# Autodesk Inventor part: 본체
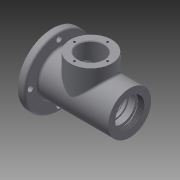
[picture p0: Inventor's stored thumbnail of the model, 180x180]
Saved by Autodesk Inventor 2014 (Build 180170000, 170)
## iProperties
Created: 2016-08
Part Number: 본체
Material: 일반
Document SubType Name: Modeling
Designer: owner
Density: 1 g/cm^3
Appearance: 기본값
Author: owner
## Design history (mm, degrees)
sketch "스케치1"
  geometry: L1 (0, 0)-(-57.5, 0); L2 (-57.5, 0)-(-57.5, 31); L3 (0, 0)-(57.5, 0); L4 (57.5, 0)-(57.5, 31); L5 (57.5, 31)-(54.5, 31); L6 (57.5, 0)-(54.5, 0); L7 (54.5, 31)-(57.5, 31); L8 (57.5, 0)-(57.5, 21); L9 (43.5, 0)-(36.2, 0); L10 (43.5, 0)-(42.8, 0); L11 (36.2, 0)-(33.5, 0); L12 (-44.5, 50)-(-44.5, 31); L13 (-54.5, 50)-(-44.5, 50); L14 (-54.5, 31)-(-54.5, 50); L15 (44.5, 31)-(54.5, 31); L16 (-57.5, 31)-(-54.5, 31); L17 (-44.5, 31)-(44.5, 31)
  constraints: 34 end point, 6 point on line, 3 perpendicular, 1 horizontal
revolve "회전1" sketch "스케치1" stored, may be unused: angle "d19" = 90 deg
sketch "스케치2"
  geometry: L1 (57.5, 0)-(57.5, 21); L2 (57.5, 0)-(43.5, 0); L3 (43.5, 0)-(36.2, 0); L4 (43.5, 0)-(42.8, 0); L5 (36.2, 0)-(33.5, 0); L6 (-45.5, 0)-(-48.5, 0); L7 (-57.5, 0)-(-36.5, 0); L8 (-57.5, 0)-(-31.5, 0); L9 (0.391, 0)-(-18.609, 0); L10 (19.391, 0)-(0.391, 0); L11 (0.391, 0)-(-29.609, 0); L12 (-57.5, 0)-(-31.5, 0); L13 (0.391, 0)-(19.391, 0); L14 (0.391, 0)-(-18.609, 0); L15 (-31.5, 0)-(28.5, 0); L16 (-57.5, 0)-(-1.5, 0); L17 (-45.491, 16.711)-(-57.5, 21); L18 (-28.2, 17.5)-(-17.5, 17.5); L19 (-17.5, 23)-(-17.5, 17.5); L20 (0, 26)-(-14.5, 26); L21 (-43.5, 12.904)-(-43.5, 13.886); L22 (-42.8, 12.5)-(-43.5, 12.904); L23 (-36.5, 12.5)-(-42.8, 12.5); L24 (-36.2, 10)-(-36.2, 12.2); L25 (-33.5, 10)-(-33.5, 13.5); L26 (-33.5, 10)-(-36.2, 10); L27 (-28.5, 16.5)-(-28.5, 17.2); L28 (-30.5, 16.5)-(-28.5, 16.5); L29 (31.5, 17.5)-(20.8, 17.5); L30 (20.5, 23)-(20.5, 17.8); L31 (1.5, 26)-(17.5, 26); L32 (57.5, 21)-(48.5, 21); L33 (45.5, 21)-(45.5, 20); L34 (33.25, 17.5)-(36.5, 17.5); L35 (33.25, 18.5)-(33.25, 17.5); L36 (31.5, 17.5)-(31.5, 18.5); L37 (31.5, 18.5)-(33.25, 18.5); L38 (36.5, 17.5)-(36.5, 20); L39 (36.5, 20)-(45.5, 20); L40 (48.5, 24)-(45.5, 24); L41 (48.5, 21)-(48.5, 24); L42 (45.5, 24)-(45.5, 21); L43 (1.5, 26)-(0, 26); L44 (-57.5, 21)-(-57.5, 0); L45 (57.5, 0)-(-28.5, 0); A1 r 3 centre (-46.5, 13.886) between (-43.5, 13.886) and (-45.491, 16.711); A2 r 0.3 centre (-36.5, 12.2) between (-36.2, 12.2) and (-36.5, 12.5); A3 r 3 centre (-30.5, 13.5) between (-30.5, 16.5) and (-33.5, 13.5); A4 r 0.3 centre (20.8, 17.8) between (20.5, 17.8) and (20.8, 17.5); A5 r 3 centre (-14.5, 23) between (-14.5, 26) and (-17.5, 23); A6 r 3 centre (17.5, 23) between (20.5, 23) and (17.5, 26); A7 r 0.3 centre (-28.2, 17.2) between (-28.2, 17.5) and (-28.5, 17.2); 6 further points
  constraints: 90 end point, 14 point on circle, 8 point on line, 7 centre point, 6 tangent, 4 horizontal, 2 perpendicular, 1 equal radius, 1 midpoint, 14 other
revolve "회전2" sketch "스케치2" stored, may be unused: angle "d62" = 90 deg
node "작업 평면1"
sketch "스케치4"
  geometry: L1 (57.5, -31)-(57.5, 0); C1 r 30 at (1.5, 0); 5 further points
  constraints: 2 end point, 1 centre point
sketch "스케치5"
  geometry: C1 r 4 at (-41.5, 0); C2 r 4 at (41.5, 0); C3 r 4 at (0, 41.5); C4 r 4 at (0, -41.5)
  constraints: 4 centre point
extrude "돌출2" cut sketch "스케치5" distance "d104" = 10; taper "d105" = 0 deg
feature "스레드2" dims "d106" = 10, "d107" = 0
fillet "모깎기1" dims "d108" = 3
node "작업 평면2"
extrude "돌출3" join sketch "스케치4" stored distance "d119" = 10; taper "d120" = 0 deg
hole "구멍4" sketch "스케치4" diameter "d121" = 3.242; stored, may be unused: countersink angle "d125" = 90 deg, drill point angle "d127" = 118 deg; dims "d122" = 8, "d123" = 4, "d124" = 2, "d126" = 10
hole "구멍5" diameter "d130" = 38; stored, may be unused: countersink angle "d134" = 90 deg, drill point angle "d136" = 0 deg; dims "d128" = 10, "d129" = 10, "d131" = 8, "d132" = 4, "d133" = 2, "d135" = 60
node "작업 평면3"
sketch "스케치7"
  geometry: L1 (-31.5, 49)-(28.5, 49) reference; L2 (-57.5, 31)-(-57.5, -31) reference; L3 (-1.5, 48.137)-(-1.5, 38.137); 2 further points
  constraints: 2 end point, 1 other
feature "엠보싱2" sketch "스케치7" dims "d141" = 0.5, "d142" = 0
fillet "모깎기2" dims "d143" = 3
chamfer "모따기2" distance "d144" = 1; stored, may be unused: second distance "d145" = 2, angle "d146" = 45 deg
node "솔리드1"
other parameters: "d64" = 49
